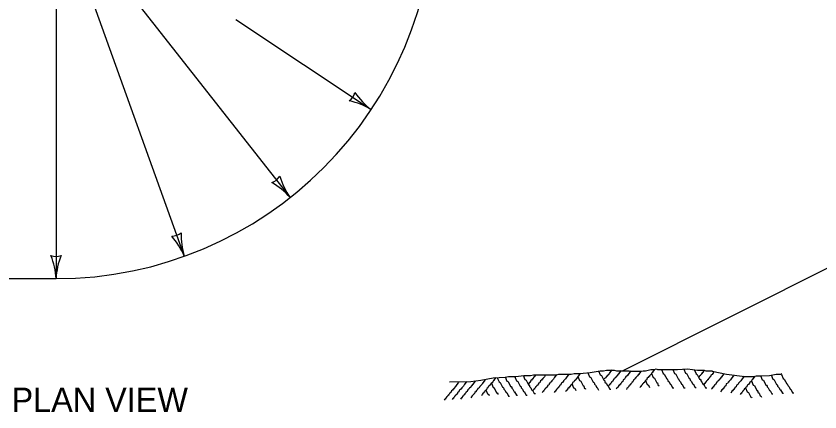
# Model space of a CAD drawing. Extents: x 49991.4 to 50021, y 49987.6 to 50011.4.
# Drawn here: x 50001.915 to 50004.569, y 50002.617 to 50003.923 of the extents above; entities that cross this region are included whole.
import ezdxf

# ---------------------------------------------------------------- set-up
doc = ezdxf.new("R2010")
doc.units = 0
for name, color, linetype in [('Level 1', 7, 'Continuous'), ('Level 2', 7, 'Continuous'), ('Level 3', 7, 'Continuous')]:
    doc.layers.add(name, color=color, linetype=linetype)

msp = doc.modelspace()

# ---------------------------------------------------------------- linework, layer by layer
at = {"layer": 'Level 1'}
for p, q in [((50006.1678, 50003.878), (50003.9187, 50002.7534)), ((50001.7071, 50003.057), (50002.0471, 50003.057)), ((50002.0471, 50003.057), (50002.0471, 50003.057)), ((50003.6293, 50002.7396), (50003.6295, 50002.7379))]:
    msp.add_line(p, q, dxfattribs=at)
for points in [[(50003.3465, 50002.7164), (50003.4167, 50002.7183), (50003.4498, 50002.7222), (50003.4907, 50002.73), (50003.5297, 50002.732), (50003.5414, 50002.7339), (50003.5648, 50002.7339), (50003.5921, 50002.7378), (50003.6136, 50002.7378), (50003.6233, 50002.7398), (50003.6681, 50002.7398), (50003.6993, 50002.7398), (50003.7071, 50002.7417), (50003.7481, 50002.7417), (50003.7578, 50002.7436), (50003.7773, 50002.7436), (50003.7871, 50002.7456), (50003.8105, 50002.7476), (50003.8436, 50002.7534), (50003.8553, 50002.7534), (50003.8651, 50002.7553), (50003.8904, 50002.7553), (50003.8982, 50002.7534), (50003.9391, 50002.7534), (50003.945, 50002.7515), (50003.9801, 50002.7515), (50003.9859, 50002.7534), (50003.9937, 50002.7534), (50004.0113, 50002.7573), (50004.023, 50002.7573), (50004.0288, 50002.7592), (50004.0327, 50002.7573), (50004.0931, 50002.7573), (50004.099, 50002.7573), (50004.1321, 50002.7592), (50004.1653, 50002.7553), (50004.1867, 50002.7553), (50004.1926, 50002.7534), (50004.2062, 50002.7534), (50004.214, 50002.7534), (50004.214, 50002.7515), (50004.2608, 50002.7417), (50004.3212, 50002.7339), (50004.3525, 50002.7339), (50004.3602, 50002.7359), (50004.3758, 50002.7359), (50004.4031, 50002.7378), (50004.4246, 50002.7417), (50004.4402, 50002.7417), (50004.4441, 50002.7436)], [(50003.8382, 50002.7529), (50003.8441, 50002.7393), (50003.848, 50002.7373), (50003.8558, 50002.7217), (50003.8578, 50002.7217), (50003.8597, 50002.7178), (50003.8597, 50002.7159), (50003.8636, 50002.712), (50003.8675, 50002.7042), (50003.8694, 50002.7042), (50003.8753, 50002.6925), (50003.8792, 50002.6925)], [(50003.8797, 50002.7568), (50003.8816, 50002.7549), (50003.8758, 50002.7471), (50003.8758, 50002.7451), (50003.8738, 50002.7451), (50003.8719, 50002.7412), (50003.866, 50002.7354), (50003.866, 50002.7334), (50003.8641, 50002.7334), (50003.8621, 50002.7295), (50003.8582, 50002.7276), (50003.8575, 50002.7254)], [(50003.9089, 50002.7539), (50003.9109, 50002.752), (50003.905, 50002.7441), (50003.905, 50002.7422), (50003.9031, 50002.7422), (50003.9011, 50002.7383), (50003.8953, 50002.7325), (50003.8953, 50002.7305), (50003.8933, 50002.7305), (50003.8914, 50002.7266), (50003.8875, 50002.7247), (50003.8855, 50002.7188), (50003.8816, 50002.7169), (50003.8816, 50002.7149), (50003.8777, 50002.711), (50003.8777, 50002.7091), (50003.8758, 50002.7091), (50003.8738, 50002.7052), (50003.8719, 50002.7052), (50003.8719, 50002.7047)], [(50003.9416, 50002.7529), (50003.9435, 50002.751), (50003.9377, 50002.7432), (50003.9377, 50002.7412), (50003.9357, 50002.7412), (50003.9338, 50002.7373), (50003.9279, 50002.7315), (50003.9279, 50002.7295), (50003.926, 50002.7295), (50003.924, 50002.7256), (50003.9201, 50002.7237), (50003.9182, 50002.7178), (50003.9143, 50002.7159), (50003.9143, 50002.7139), (50003.9104, 50002.71), (50003.9104, 50002.7081), (50003.9084, 50002.7081), (50003.9065, 50002.7042), (50003.9045, 50002.7042), (50003.9045, 50002.7022), (50003.9006, 50002.6983), (50003.9006, 50002.6964), (50003.8987, 50002.6964), (50003.8967, 50002.6925)], [(50004.02, 50002.7578), (50004.022, 50002.7559), (50004.0161, 50002.7481), (50004.0161, 50002.7461), (50004.0142, 50002.7461), (50004.0122, 50002.7422), (50004.0064, 50002.7364), (50004.0064, 50002.7344), (50004.0045, 50002.7344), (50004.0025, 50002.7305), (50003.9986, 50002.7286), (50003.9966, 50002.7227), (50003.9927, 50002.7208), (50003.9927, 50002.7188), (50003.9888, 50002.7149), (50003.9888, 50002.713), (50003.9869, 50002.713), (50003.985, 50002.7091), (50003.983, 50002.7091), (50003.983, 50002.7071), (50003.9791, 50002.7032), (50003.9791, 50002.7013), (50003.9771, 50002.7013), (50003.9752, 50002.6973)], [(50004.0459, 50002.7573), (50004.0517, 50002.7436), (50004.0556, 50002.7417), (50004.0634, 50002.7261), (50004.0654, 50002.7261), (50004.0673, 50002.7222), (50004.0673, 50002.7203), (50004.0712, 50002.7164), (50004.0751, 50002.7086), (50004.0771, 50002.7086), (50004.0829, 50002.6969), (50004.0868, 50002.6969)], [(50004.0834, 50002.7578), (50004.0893, 50002.7441), (50004.0932, 50002.7422), (50004.1009, 50002.7266), (50004.1029, 50002.7266), (50004.1049, 50002.7227), (50004.1049, 50002.7207), (50004.1088, 50002.7168), (50004.1126, 50002.709), (50004.1146, 50002.709), (50004.1204, 50002.6973), (50004.1244, 50002.6973)], [(50004.12, 50002.7588), (50004.1258, 50002.7451), (50004.1297, 50002.7432), (50004.1375, 50002.7276), (50004.1395, 50002.7276), (50004.1414, 50002.7237), (50004.1414, 50002.7217), (50004.1453, 50002.7178), (50004.1492, 50002.71), (50004.1512, 50002.71), (50004.157, 50002.6983), (50004.1609, 50002.6983)], [(50004.1546, 50002.7568), (50004.1604, 50002.7432), (50004.1643, 50002.7412), (50004.1721, 50002.7256), (50004.1741, 50002.7256), (50004.176, 50002.7217), (50004.176, 50002.7198), (50004.1799, 50002.7159), (50004.1838, 50002.7081), (50004.1858, 50002.7081), (50004.1916, 50002.6964), (50004.1955, 50002.6964)], [(50004.1873, 50002.7531), (50004.1838, 50002.7495), (50004.1838, 50002.7476), (50004.1819, 50002.7476), (50004.1799, 50002.7436), (50004.1779, 50002.7436), (50004.1779, 50002.7417), (50004.1741, 50002.7378), (50004.1741, 50002.7359), (50004.1721, 50002.7359), (50004.1702, 50002.732)], [(50003.4966, 50002.7315), (50003.4985, 50002.7295), (50003.4927, 50002.7217), (50003.4927, 50002.7198), (50003.4907, 50002.7198), (50003.4888, 50002.7159), (50003.4829, 50002.71), (50003.4829, 50002.7081), (50003.481, 50002.7081), (50003.479, 50002.7042), (50003.4751, 50002.7022), (50003.4732, 50002.6964), (50003.4693, 50002.6944), (50003.4693, 50002.6925), (50003.4654, 50002.6886), (50003.4654, 50002.6866), (50003.4634, 50002.6866), (50003.4615, 50002.6827), (50003.4595, 50002.6827), (50003.4595, 50002.6808), (50003.4556, 50002.6769), (50003.4556, 50002.6749), (50003.4537, 50002.6749), (50003.4518, 50002.671)], [(50003.5039, 50002.73), (50003.5097, 50002.7164), (50003.5136, 50002.7144), (50003.5214, 50002.6988), (50003.5234, 50002.6988), (50003.5253, 50002.6949), (50003.5253, 50002.693), (50003.5292, 50002.6891), (50003.5331, 50002.6813), (50003.5351, 50002.6813), (50003.5409, 50002.6696), (50003.5448, 50002.6696)], [(50003.5302, 50002.7329), (50003.5361, 50002.7193), (50003.54, 50002.7173), (50003.5477, 50002.7017), (50003.5497, 50002.7017), (50003.5517, 50002.6978), (50003.5517, 50002.6959), (50003.5556, 50002.692), (50003.5594, 50002.6842), (50003.5614, 50002.6842), (50003.5673, 50002.6725), (50003.5712, 50002.6725)], [(50003.5619, 50002.7334), (50003.5677, 50002.7198), (50003.5717, 50002.7178), (50003.5794, 50002.7022), (50003.5814, 50002.7022), (50003.5833, 50002.6983), (50003.5833, 50002.6964), (50003.5872, 50002.6925), (50003.5911, 50002.6847), (50003.5931, 50002.6847), (50003.5989, 50002.673), (50003.6028, 50002.673)], [(50003.5892, 50002.7383), (50003.595, 50002.7247), (50003.5989, 50002.7227), (50003.6067, 50002.7071), (50003.6087, 50002.7071), (50003.6106, 50002.7032), (50003.6106, 50002.7013), (50003.6145, 50002.6973), (50003.6184, 50002.6896), (50003.6204, 50002.6896), (50003.6262, 50002.6779), (50003.6301, 50002.6779)], [(50003.6298, 50002.7386), (50003.6287, 50002.7354), (50003.6248, 50002.7334), (50003.6248, 50002.7315), (50003.6209, 50002.7276), (50003.6209, 50002.7257), (50003.6189, 50002.7257), (50003.617, 50002.7217), (50003.615, 50002.7217), (50003.615, 50002.7198), (50003.6111, 50002.7159), (50003.6111, 50002.7139), (50003.6092, 50002.7139), (50003.6072, 50002.71)], [(50003.6638, 50002.7383), (50003.6638, 50002.7373), (50003.6618, 50002.7373), (50003.6599, 50002.7334), (50003.654, 50002.7276), (50003.654, 50002.7257), (50003.6521, 50002.7257), (50003.6501, 50002.7217), (50003.6462, 50002.7198), (50003.6443, 50002.7139), (50003.6404, 50002.712), (50003.6404, 50002.71), (50003.6365, 50002.7062), (50003.6365, 50002.7042), (50003.6345, 50002.7042), (50003.6326, 50002.7003), (50003.6306, 50002.7003), (50003.6306, 50002.6983), (50003.6267, 50002.6944), (50003.6267, 50002.6925), (50003.6248, 50002.6925), (50003.6228, 50002.6886)], [(50003.6974, 50002.7412), (50003.6993, 50002.7393), (50003.6935, 50002.7315), (50003.6935, 50002.7295), (50003.6915, 50002.7295), (50003.6896, 50002.7256), (50003.6837, 50002.7198), (50003.6837, 50002.7178), (50003.6818, 50002.7178), (50003.6798, 50002.7139), (50003.676, 50002.712), (50003.674, 50002.7062), (50003.6701, 50002.7042), (50003.6701, 50002.7022), (50003.6662, 50002.6983), (50003.6662, 50002.6964), (50003.6642, 50002.6964), (50003.6623, 50002.6925), (50003.6604, 50002.6925), (50003.6604, 50002.6906), (50003.6564, 50002.6866), (50003.6564, 50002.6847), (50003.6545, 50002.6847), (50003.6526, 50002.6808)], [(50003.7369, 50002.7417), (50003.7388, 50002.7398), (50003.733, 50002.732), (50003.733, 50002.73), (50003.731, 50002.73), (50003.7291, 50002.7261), (50003.7232, 50002.7203), (50003.7232, 50002.7183), (50003.7213, 50002.7183), (50003.7193, 50002.7144), (50003.7154, 50002.7125), (50003.7135, 50002.7066), (50003.7096, 50002.7047), (50003.7096, 50002.7027), (50003.7057, 50002.6988), (50003.7057, 50002.6969), (50003.7037, 50002.6969), (50003.7018, 50002.693), (50003.6998, 50002.693), (50003.6998, 50002.691), (50003.6959, 50002.6871), (50003.6959, 50002.6852), (50003.694, 50002.6852), (50003.692, 50002.6813)], [(50003.7744, 50002.7441), (50003.7763, 50002.7422), (50003.7705, 50002.7344), (50003.7705, 50002.7325), (50003.7685, 50002.7325), (50003.7666, 50002.7285), (50003.7607, 50002.7227), (50003.7607, 50002.7208), (50003.7588, 50002.7208), (50003.7568, 50002.7169), (50003.7529, 50002.7149), (50003.751, 50002.7091), (50003.7471, 50002.7071), (50003.7471, 50002.7052), (50003.7432, 50002.7013), (50003.7432, 50002.6993), (50003.7413, 50002.6993), (50003.7393, 50002.6954), (50003.7374, 50002.6954), (50003.7374, 50002.6935), (50003.7335, 50002.6896), (50003.7335, 50002.6876), (50003.7315, 50002.6876), (50003.7295, 50002.6837)], [(50003.77, 50002.7344), (50003.7759, 50002.7207), (50003.7798, 50002.7188), (50003.7876, 50002.7032), (50003.7895, 50002.7032), (50003.7914, 50002.6993), (50003.7914, 50002.6973), (50003.7954, 50002.6934), (50003.7958, 50002.6925)], [(50003.8032, 50002.7466), (50003.809, 50002.7329), (50003.8129, 50002.731), (50003.8207, 50002.7154), (50003.8227, 50002.7154), (50003.8246, 50002.7115), (50003.8246, 50002.7095), (50003.8285, 50002.7056), (50003.8324, 50002.6978), (50003.8343, 50002.6978), (50003.8384, 50002.6897)], [(50003.9752, 50002.752), (50003.9771, 50002.75), (50003.9713, 50002.7422), (50003.9713, 50002.7402), (50003.9694, 50002.7402), (50003.9674, 50002.7364), (50003.9616, 50002.7305), (50003.9616, 50002.7286), (50003.9596, 50002.7286), (50003.9576, 50002.7247), (50003.9538, 50002.7227), (50003.9518, 50002.7169), (50003.9479, 50002.7149), (50003.9479, 50002.7129), (50003.944, 50002.7091), (50003.944, 50002.7071), (50003.9421, 50002.7071), (50003.9401, 50002.7032), (50003.9382, 50002.7032), (50003.9382, 50002.7013), (50003.9343, 50002.6973), (50003.9343, 50002.6954), (50003.9323, 50002.6954), (50003.9304, 50002.6915)], [(50004.0132, 50002.7441), (50004.0191, 50002.7305), (50004.023, 50002.7285), (50004.0308, 50002.7129), (50004.0327, 50002.7129), (50004.0347, 50002.709), (50004.0347, 50002.7071), (50004.0383, 50002.7035)], [(50004.219, 50002.7482), (50004.2174, 50002.7466), (50004.2174, 50002.7446), (50004.2155, 50002.7446), (50004.2135, 50002.7407), (50004.2096, 50002.7388), (50004.2077, 50002.7329), (50004.2038, 50002.731), (50004.2038, 50002.729), (50004.1999, 50002.7252), (50004.1999, 50002.7232), (50004.1979, 50002.7232), (50004.196, 50002.7193), (50004.194, 50002.7193), (50004.194, 50002.7173), (50004.1901, 50002.7134), (50004.1901, 50002.7115), (50004.1882, 50002.7115), (50004.1863, 50002.7076)], [(50004.2491, 50002.7441), (50004.2511, 50002.7422), (50004.2452, 50002.7344), (50004.2452, 50002.7325), (50004.2433, 50002.7325), (50004.2413, 50002.7285), (50004.2355, 50002.7227), (50004.2355, 50002.7208), (50004.2335, 50002.7208), (50004.2316, 50002.7169), (50004.2277, 50002.7149), (50004.2257, 50002.7091), (50004.2218, 50002.7071), (50004.2218, 50002.7052), (50004.2179, 50002.7013), (50004.2179, 50002.6993), (50004.216, 50002.6993), (50004.214, 50002.6954), (50004.2121, 50002.6954), (50004.2121, 50002.6935), (50004.2115, 50002.6929)], [(50004.2818, 50002.7388), (50004.2837, 50002.7368), (50004.2779, 50002.729), (50004.2779, 50002.7271), (50004.2759, 50002.7271), (50004.274, 50002.7232), (50004.2681, 50002.7173), (50004.2681, 50002.7154), (50004.2662, 50002.7154), (50004.2642, 50002.7115), (50004.2603, 50002.7096), (50004.2584, 50002.7037), (50004.2545, 50002.7017), (50004.2545, 50002.6998), (50004.2506, 50002.6959), (50004.2506, 50002.6939), (50004.2486, 50002.6939), (50004.2467, 50002.6901), (50004.2447, 50002.6901), (50004.2447, 50002.6881), (50004.2408, 50002.6842)], [(50004.3159, 50002.7354), (50004.3178, 50002.7334), (50004.312, 50002.7256), (50004.312, 50002.7237), (50004.3101, 50002.7237), (50004.3081, 50002.7198), (50004.3022, 50002.7139), (50004.3022, 50002.712), (50004.3003, 50002.712), (50004.2983, 50002.7081), (50004.2945, 50002.7062), (50004.2925, 50002.7003), (50004.2886, 50002.6983), (50004.2886, 50002.6964), (50004.2847, 50002.6925), (50004.2847, 50002.6906), (50004.2827, 50002.6906), (50004.2808, 50002.6866), (50004.2788, 50002.6866), (50004.2788, 50002.6847), (50004.275, 50002.6808), (50004.275, 50002.6801)], [(50004.351, 50002.7349), (50004.3529, 50002.7329), (50004.3471, 50002.7252), (50004.3471, 50002.7232), (50004.3451, 50002.7232), (50004.3432, 50002.7193), (50004.3373, 50002.7134), (50004.3373, 50002.7115), (50004.3354, 50002.7115), (50004.3334, 50002.7076), (50004.3296, 50002.7057), (50004.3276, 50002.6998), (50004.3237, 50002.6978), (50004.3237, 50002.6959), (50004.3198, 50002.692), (50004.3198, 50002.6901), (50004.3178, 50002.6901), (50004.3159, 50002.6862), (50004.3139, 50002.6862), (50004.3139, 50002.6842), (50004.3101, 50002.6803), (50004.3101, 50002.6783), (50004.3081, 50002.6783), (50004.3061, 50002.6744)], [(50004.3734, 50002.7373), (50004.3792, 50002.7237), (50004.3832, 50002.7217), (50004.391, 50002.7062), (50004.3929, 50002.7062), (50004.3948, 50002.7022), (50004.3948, 50002.7003), (50004.3988, 50002.6964), (50004.4027, 50002.6886), (50004.4046, 50002.6886), (50004.4104, 50002.6769), (50004.4144, 50002.6769)], [(50004.4085, 50002.7392), (50004.4144, 50002.7256), (50004.4182, 50002.7237), (50004.426, 50002.7081), (50004.428, 50002.7081), (50004.4299, 50002.7042), (50004.4299, 50002.7022), (50004.4338, 50002.6983), (50004.4377, 50002.6905), (50004.4397, 50002.6905), (50004.4455, 50002.6788), (50004.4494, 50002.6788)], [(50004.4421, 50002.7412), (50004.448, 50002.7276), (50004.4519, 50002.7256), (50004.4597, 50002.71), (50004.4616, 50002.71), (50004.4636, 50002.7061), (50004.4636, 50002.7042), (50004.4675, 50002.7003), (50004.4714, 50002.6925), (50004.4733, 50002.6925), (50004.4792, 50002.6808), (50004.4831, 50002.6808)], [(50003.3738, 50002.7164), (50003.3757, 50002.7144), (50003.3699, 50002.7066), (50003.3699, 50002.7047), (50003.3679, 50002.7047), (50003.366, 50002.7008), (50003.3601, 50002.6949), (50003.3601, 50002.693), (50003.3582, 50002.693), (50003.3562, 50002.6891), (50003.3523, 50002.6871), (50003.3504, 50002.6813), (50003.3465, 50002.6793), (50003.3465, 50002.6774), (50003.3426, 50002.6735), (50003.3426, 50002.6715), (50003.3406, 50002.6715), (50003.3387, 50002.6676), (50003.3367, 50002.6676), (50003.3367, 50002.6657), (50003.3328, 50002.6618), (50003.3328, 50002.6598), (50003.3309, 50002.6598), (50003.3289, 50002.6559)], [(50003.4001, 50002.7183), (50003.402, 50002.7164), (50003.3962, 50002.7086), (50003.3962, 50002.7066), (50003.3942, 50002.7066), (50003.3923, 50002.7027), (50003.3865, 50002.6969), (50003.3865, 50002.6949), (50003.3845, 50002.6949), (50003.3825, 50002.691), (50003.3786, 50002.6891), (50003.3767, 50002.6832), (50003.3728, 50002.6813), (50003.3728, 50002.6793), (50003.3689, 50002.6754), (50003.3689, 50002.6735), (50003.3669, 50002.6735), (50003.365, 50002.6696), (50003.363, 50002.6696), (50003.363, 50002.6676), (50003.3591, 50002.6637), (50003.3591, 50002.6618), (50003.3572, 50002.6618), (50003.3553, 50002.6579)], [(50003.4279, 50002.7198), (50003.4298, 50002.7178), (50003.4239, 50002.71), (50003.4239, 50002.7081), (50003.422, 50002.7081), (50003.4201, 50002.7042), (50003.4142, 50002.6983), (50003.4142, 50002.6964), (50003.4123, 50002.6964), (50003.4103, 50002.6925), (50003.4064, 50002.6905), (50003.4045, 50002.6847), (50003.4006, 50002.6827), (50003.4006, 50002.6808), (50003.3967, 50002.6769), (50003.3967, 50002.6749), (50003.3947, 50002.6749), (50003.3928, 50002.671), (50003.3908, 50002.671), (50003.3908, 50002.6691), (50003.3869, 50002.6652), (50003.3869, 50002.6632), (50003.385, 50002.6632), (50003.383, 50002.6593)], [(50003.4615, 50002.7242), (50003.4634, 50002.7222), (50003.4576, 50002.7144), (50003.4576, 50002.7125), (50003.4556, 50002.7125), (50003.4537, 50002.7086), (50003.4479, 50002.7027), (50003.4479, 50002.7008), (50003.4459, 50002.7008), (50003.4439, 50002.6969), (50003.44, 50002.6949), (50003.4381, 50002.6891), (50003.4342, 50002.6871), (50003.4342, 50002.6852), (50003.4303, 50002.6813), (50003.4303, 50002.6793), (50003.4284, 50002.6793), (50003.4264, 50002.6754), (50003.4244, 50002.6754), (50003.4244, 50002.6735), (50003.4205, 50002.6696), (50003.4205, 50002.6676), (50003.4186, 50002.6676), (50003.4167, 50002.6637)], [(50003.4844, 50002.712), (50003.4903, 50002.6983), (50003.4942, 50002.6964), (50003.5019, 50002.6808), (50003.5039, 50002.6808), (50003.5058, 50002.6769), (50003.5058, 50002.6752)], [(50003.75, 50002.711), (50003.7559, 50002.6973), (50003.7598, 50002.6954), (50003.7637, 50002.6876)], [(50003.9932, 50002.7212), (50003.9991, 50002.7076), (50004.003, 50002.7056), (50004.0068, 50002.6981)], [(50004.3432, 50002.7198), (50004.349, 50002.7061), (50004.3529, 50002.7042), (50004.3607, 50002.6886), (50004.3627, 50002.6886), (50004.3646, 50002.6847), (50004.3646, 50002.6827), (50004.3685, 50002.6788), (50004.3724, 50002.671), (50004.3744, 50002.671), (50004.3766, 50002.6666)], [(50003.4659, 50002.6905), (50003.4717, 50002.6769), (50003.4756, 50002.6749), (50003.4772, 50002.6718)], [(50004.3237, 50002.6969), (50004.3296, 50002.6832), (50004.3334, 50002.6813), (50004.3412, 50002.6657), (50004.3432, 50002.6657), (50004.3443, 50002.6634)]]:
    msp.add_lwpolyline(points, dxfattribs=at)
msp.add_arc((50002.0471, 50004.307), 1.25, 270, 0, dxfattribs=at)
at = {"layer": 'Level 3'}
for p, q in [((50002.0471, 50004.307), (50002.8198, 50003.3245)), ((50002.0471, 50004.307), (50002.4704, 50003.1309)), ((50002.0471, 50004.307), (50002.0471, 50003.057)), ((50002.6412, 50003.9118), (50003.0879, 50003.6148))]:
    msp.add_line(p, q, dxfattribs=at)
for centre, radius, start, end in [((50002.9812, 50003.6858), 0.0548, 308.515, 344.2373), ((50003.2186, 50003.7947), 0.2223, 213.8321, 234.0157), ((50002.9686, 50003.4147), 0.233, 59.2034, 78.4533), ((50002.7406, 50003.4253), 0.0548, 290.3226, 326.0449), ((50003.0001, 50003.4546), 0.2223, 195.6398, 215.8233), ((50002.644, 50003.1716), 0.233, 41.0111, 60.2609), ((50002.427, 50003.2515), 0.0548, 271.9336, 307.6559), ((50002.6825, 50003.1975), 0.2223, 177.2507, 197.4343), ((50002.2553, 50003.0413), 0.233, 22.622, 41.8719), ((50002.0471, 50003.1852), 0.0548, 252.1388, 287.8612), ((50001.8144, 50003.0455), 0.233, 2.8273, 22.0772), ((50002.2692, 50003.0479), 0.2223, 157.456, 177.6395)]:
    msp.add_arc(centre, radius, start, end, dxfattribs=at)

# ---------------------------------------------------------------- texts
at = {"layer": 'Level 2'}
msp.add_text('PLAN VIEW', height=0.08, dxfattribs=at).set_placement((50001.9, 50002.6175))

doc.saveas('drawing.dxf')
